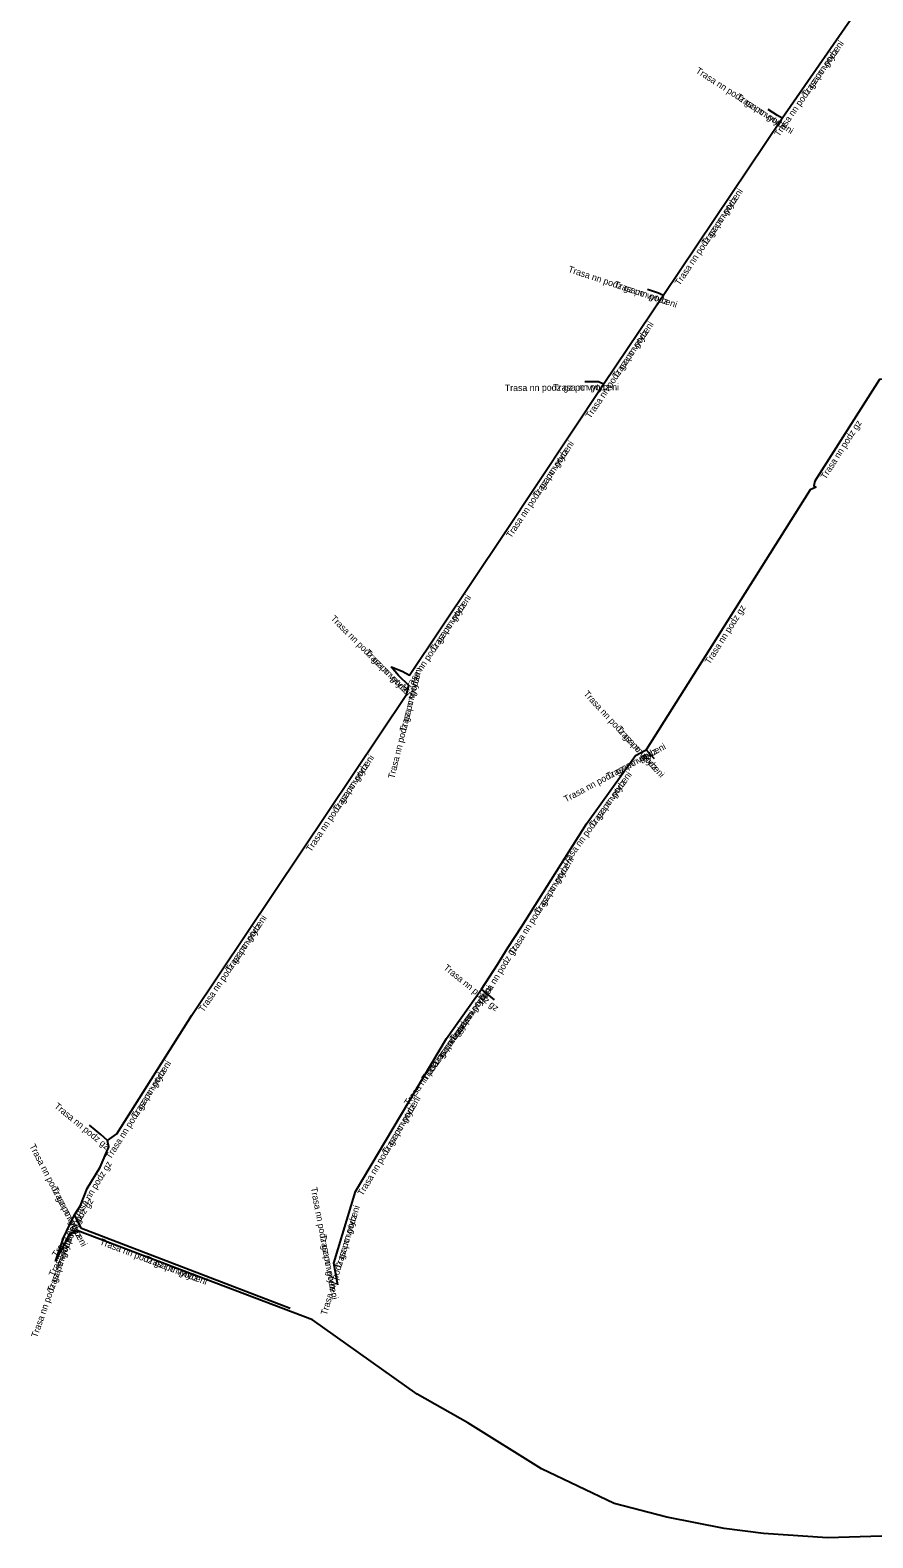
# Model space of a CAD drawing. Extents: x -672293 to -672171, y -1013397 to -1013222.
# Drawn here: x -672292.2 to -672228, y -1013396.5 to -1013281.7 of the extents above; entities that cross this region are included whole.
import ezdxf

# ---------------------------------------------------------------- set-up
doc = ezdxf.new("R2010")
doc.units = 0
for name, color, linetype in [('Popiskový text - Ostatní atributy Trasy', 7, 'Continuous'), ('Spojnice NN', 7, 'Continuous'), ('Spojnice VN', 7, 'Continuous')]:
    doc.layers.add(name, color=color, linetype=linetype)

msp = doc.modelspace()

# ---------------------------------------------------------------- linework, layer by layer
at = {"layer": 'Spojnice NN'}
for points in [[(-672234.89, -1013288.38), (-672228.6, -1013279.32)], [(-672234.89, -1013288.38), (-672228.6, -1013279.32)], [(-672234.89, -1013288.38), (-672235.24, -1013288.18), (-672235.95, -1013287.72)], [(-672234.89, -1013288.38), (-672235.24, -1013288.18), (-672235.95, -1013287.72)], [(-672243.95, -1013301.89), (-672234.89, -1013288.38)], [(-672243.95, -1013301.89), (-672234.89, -1013288.38)], [(-672248.48, -1013308.65), (-672243.95, -1013301.89)], [(-672248.48, -1013308.65), (-672243.95, -1013301.89)], [(-672243.95, -1013301.89), (-672244.3, -1013301.7), (-672245.14, -1013301.43)], [(-672243.95, -1013301.89), (-672244.3, -1013301.7), (-672245.14, -1013301.43)], [(-672256.09, -1013320.08), (-672248.48, -1013308.65)], [(-672256.09, -1013320.08), (-672248.48, -1013308.65)], [(-672248.48, -1013308.65), (-672248.87, -1013308.47), (-672249.9, -1013308.48)], [(-672248.48, -1013308.65), (-672248.87, -1013308.47), (-672249.9, -1013308.48)], [(-672227.26, -1013308.27), (-672227.46, -1013308.28), (-672227.64, -1013308.56), (-672232.4, -1013316.03), (-672232.48, -1013316.38), (-672232.3, -1013316.49)], [(-672232.3, -1013316.49), (-672232.74, -1013316.7), (-672238.46, -1013325.76), (-672245.24, -1013336.5)], [(-672264.66, -1013330.17), (-672263.81, -1013330.5), (-672263.27, -1013330.81), (-672256.09, -1013320.08)], [(-672264.66, -1013330.17), (-672263.81, -1013330.5), (-672263.27, -1013330.81), (-672256.09, -1013320.08)], [(-672263.32, -1013331.61), (-672264.09, -1013330.84), (-672264.66, -1013330.17)], [(-672263.32, -1013331.61), (-672264.09, -1013330.84), (-672264.66, -1013330.17)], [(-672263.49, -1013332.29), (-672263.32, -1013331.61)], [(-672263.49, -1013332.29), (-672263.32, -1013331.61)], [(-672271.52, -1013344.27), (-672263.49, -1013332.29)], [(-672271.52, -1013344.27), (-672263.49, -1013332.29)], [(-672249.78, -1013342.14), (-672246.04, -1013336.93)], [(-672249.78, -1013342.14), (-672246.04, -1013336.93)], [(-672246.04, -1013336.93), (-672245.24, -1013336.5)], [(-672246.04, -1013336.93), (-672245.24, -1013336.5)], [(-672244.61, -1013337.19), (-672245.24, -1013336.5)], [(-672244.61, -1013337.19), (-672245.24, -1013336.5)], [(-672254.72, -1013350), (-672249.78, -1013342.14)], [(-672254.72, -1013350), (-672249.78, -1013342.14)], [(-672279.85, -1013356.71), (-672271.52, -1013344.27)], [(-672279.85, -1013356.71), (-672271.52, -1013344.27)], [(-672257.77, -1013354.74), (-672256.55, -1013352.86), (-672255.74, -1013351.53), (-672254.72, -1013350)], [(-672259.32, -1013356.92), (-672257.77, -1013354.74)], [(-672259.32, -1013356.92), (-672257.77, -1013354.74)], [(-672256.79, -1013355.54), (-672257.77, -1013354.74)], [(-672286.25, -1013366.28), (-672285.55, -1013365.77), (-672279.85, -1013356.71)], [(-672286.25, -1013366.28), (-672285.55, -1013365.77), (-672279.85, -1013356.71)], [(-672260.44, -1013358.49), (-672259.32, -1013356.92)], [(-672260.44, -1013358.49), (-672259.32, -1013356.92)], [(-672267.37, -1013370.16), (-672260.44, -1013358.49)], [(-672267.37, -1013370.16), (-672260.44, -1013358.49)], [(-672286.25, -1013366.28), (-672286.78, -1013365.81), (-672287.64, -1013365.11)], [(-672288.31, -1013371.23), (-672287.81, -1013369.93), (-672286.83, -1013368.3), (-672286.15, -1013366.76), (-672286.25, -1013366.28)], [(-672269.03, -1013375.62), (-672267.37, -1013370.16)], [(-672269.03, -1013375.62), (-672267.37, -1013370.16)], [(-672289.68, -1013373.84), (-672288.77, -1013371.94)], [(-672288.77, -1013371.94), (-672288.31, -1013371.23)], [(-672288.24, -1013372.96), (-672288.77, -1013371.94)], [(-672288.24, -1013372.96), (-672288.77, -1013371.94)], [(-672272.34, -1013379.06), (-672288.24, -1013372.96)], [(-672272.34, -1013379.06), (-672288.24, -1013372.96)], [(-672289.68, -1013373.84), (-672290.26, -1013375.49)], [(-672289.68, -1013373.84), (-672290.26, -1013375.49)], [(-672268.71, -1013377.3), (-672269.03, -1013375.62)], [(-672268.71, -1013377.3), (-672269.03, -1013375.62)]]:
    msp.add_lwpolyline(points, dxfattribs=at)
at = {"layer": 'Spojnice VN'}
msp.add_lwpolyline([(-672225.64, -1013396.36), (-672231.43, -1013396.54), (-672236.31, -1013396.2), (-672239.31, -1013395.83), (-672243.67, -1013394.97), (-672247.67, -1013393.93), (-672253.21, -1013391.28), (-672258.82, -1013387.79), (-672262.68, -1013385.59), (-672270.64, -1013379.92), (-672288.53, -1013373.15), (-672289.19, -1013373.42), (-672290.26, -1013375.49)], dxfattribs=at)

# ---------------------------------------------------------------- texts
at = {"layer": 'Popiskový text - Ostatní atributy Trasy'}
for s, rotation, p in [('Trasa nn podz gz po vytyceni', 55.2293, (-672235.11, -1013289.83)), ('Trasa nn podz', 55.2293, (-672233.01, -1013286.81)), ('Trasa nn podz gz po vytyceni', 327.01, (-672241.51, -1013284.88)), ('Trasa nn podz', 327.01, (-672238.42, -1013286.89)), ('Trasa nn podz gz po vytyceni', 56.1536, (-672242.69, -1013301.17)), ('Trasa nn podz', 56.1536, (-672240.63, -1013298.11)), ('Trasa nn podz gz po vytyceni', 341.6164, (-672251.22, -1013300.09)), ('Trasa nn podz', 341.6164, (-672247.72, -1013301.25)), ('Trasa nn podz gz po vytyceni', 56.1732, (-672249.48, -1013311.31)), ('Trasa nn podz', 56.1732, (-672247.43, -1013308.25)), ('Trasa nn podz gz po vytyceni', 0.471, (-672256, -1013309.18)), ('Trasa nn podz', 0.471, (-672252.31, -1013309.15)), ('Trasa nn podz gz', 57.4941, (-672231.57, -1013315.94)), ('Trasa nn podz gz po vytyceni', 56.3447, (-672255.53, -1013320.41)), ('Trasa nn podz', 56.3447, (-672253.49, -1013317.35)), ('Trasa nn podz gz po vytyceni', 56.2102, (-672263.37, -1013332.12)), ('Trasa nn podz', 56.2102, (-672261.32, -1013329.06)), ('Trasa nn podz gz', 57.7364, (-672240.39, -1013330.03)), ('Trasa nn podz gz po vytyceni', 315, (-672269.31, -1013326.54)), ('Trasa nn podz', 315, (-672266.7, -1013329.15)), ('Trasa nn podz gz po vytyceni', 75.9638, (-672264.43, -1013338.74)), ('Trasa nn podz', 75.9638, (-672263.54, -1013335.16)), ('Trasa nn podz gz po vytyceni', 312.725, (-672250.04, -1013332.27)), ('Trasa nn podz', 312.725, (-672247.54, -1013334.97)), ('Trasa nn podz gz po vytyceni', 28.258, (-672251.35, -1013340.52)), ('Trasa nn podz', 28.258, (-672248.11, -1013338.78)), ('Trasa nn podz gz po vytyceni', 56.1667, (-672270.77, -1013344.32)), ('Trasa nn podz', 56.1667, (-672268.72, -1013341.26)), ('Trasa nn podz gz po vytyceni', 54.3273, (-672251.37, -1013345.46)), ('Trasa nn podz', 54.3273, (-672249.22, -1013342.47)), ('Trasa nn podz gz po vytyceni', 57.8507, (-672255.34, -1013352.2)), ('Trasa nn podz', 57.8507, (-672253.37, -1013349.08)), ('Trasa nn podz gz po vytyceni', 56.1932, (-672278.95, -1013356.53)), ('Trasa nn podz', 56.1932, (-672276.9, -1013353.47)), ('Trasa nn podz gz', 58.6576, (-672257.72, -1013356.03)), ('Trasa nn podz gz', 320.7743, (-672260.71, -1013353.18)), ('Trasa nn podz gz po vytyceni', 54.5491, (-672261.98, -1013361.77)), ('Trasa nn podz', 54.5491, (-672259.84, -1013358.77)), ('Trasa nn podz gz po vytyceni', 54.5492, (-672263.31, -1013363.65)), ('Trasa nn podz', 54.5492, (-672261.18, -1013360.65)), ('Trasa nn podz gz po vytyceni', 57.8244, (-672286.02, -1013367.74)), ('Trasa nn podz', 57.8244, (-672284.06, -1013364.62)), ('Trasa nn podz gz po vytyceni', 59.2969, (-672266.83, -1013370.53)), ('Trasa nn podz gz', 320.7727, (-672290.36, -1013363.73)), ('Trasa nn podz', 59.2969, (-672264.95, -1013367.36)), ('Trasa nn podz gz po vytyceni', 297.4567, (-672292.23, -1013366.69)), ('Trasa nn podz gz', 58.9846, (-672288.57, -1013372.45)), ('Trasa nn podz', 297.4567, (-672290.53, -1013369.96)), ('Trasa nn podz gz', 57.0613, (-672290.11, -1013375.21)), ('Trasa nn podz gz po vytyceni', 280.7843, (-672270.79, -1013369.87)), ('Trasa nn podz gz', 64.408, (-672290.32, -1013376.68)), ('Trasa nn podz gz po vytyceni', 73.0892, (-672269.57, -1013379.62)), ('Trasa nn podz', 73.0892, (-672268.49, -1013376.09)), ('Trasa nn podz gz po vytyceni', 70.6327, (-672291.62, -1013381.33)), ('Trasa nn podz', 70.6327, (-672290.4, -1013377.85)), ('Trasa nn podz gz po vytyceni', 339.0108, (-672286.9, -1013374.17)), ('Trasa nn podz', 280.7843, (-672270.1, -1013373.49)), ('Trasa nn podz', 339.0108, (-672283.46, -1013375.49))]:
    msp.add_text(s, height=0.5, rotation=rotation, dxfattribs=at).set_placement(p)

doc.saveas('drawing.dxf')
